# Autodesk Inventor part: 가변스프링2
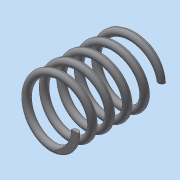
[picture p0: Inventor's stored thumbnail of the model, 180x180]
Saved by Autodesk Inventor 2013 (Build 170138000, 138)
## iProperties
Created: 2018-10
Part Number: 가변스프링2
Material: 일반
Document SubType Name: Modeling
Designer: Administrator
Density: 1 g/cm^3
Author: Administrator
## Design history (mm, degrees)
sketch "스케치1"
  geometry: L1 (0, 0)-(0, -24.527); L2 (8, 0)-(0, 0); L3 (0, -24.527)-(8, -24.527); C1 r 1 at (8, 0)
  constraints: 6 end point, 1 centre point, 1 horizontal alignment, 1 parallel, 1 perpendicular, 1 vertical
  dimensions: "d0" = 24.52707 distance of L1.start L1.end (derived); "d1" = 2 diameter of C1; "d2" = 16 diameter of L2.start L1; "d3" = 8 distance of L1.end L3.end
feature "코일1" sketch "스케치1" pitch "d4" = 10; turns "d6" = 5; dims "d5" = 24.52707 (= d0), "d7" = 0, angle "d8" = 90 deg, angle "d9" = 90 deg, "d10" = 0, "d11" = 0
sketch "스케치2"
  geometry: L1 (-24.527, 10)-(0, 10); L2 (0, 10)-(0, -10); L3 (0, -10)-(-24.527, -10); L4 (-24.527, -10)-(-24.527, 10); 2 further points
  constraints: 8 end point, 2 parallel, 1 coincident, 1 horizontal, 1 midpoint, 1 perpendicular
  dimensions: "d12" = 24.52707 distance of L2.end L3.end (derived); "d14" = 20 distance of L1.end L2.end
extrude "돌출1" sketch "스케치2" stored distance "d15" = 0; taper "d16" = 0 deg
node "솔리드1"
